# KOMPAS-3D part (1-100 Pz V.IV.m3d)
File: created 05.08.2017 09:44:06, last saved 05.08.2017 10:24:03.
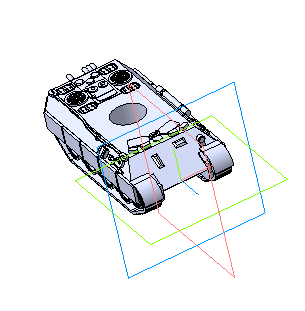
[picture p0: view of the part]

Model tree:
1. Операция без истории:1
2. Вырезать элемент выдавливания:1
     Расстояние 1 = 20
3. Вырезать элемент выдавливания:2
     Расстояние 1 = 20
4. Операция выдавливания:1
     Расстояние 1 = 0.1; Расстояние 2 = 1
5. Вырезать элемент выдавливания:3
     Расстояние 1 = 20
6. Вырезать элемент выдавливания:4
     Расстояние 1 = 17
7. Вырезать элемент выдавливания:5
     Расстояние 1 = 17
8. Вырезать элемент выдавливания:11
     Расстояние 1 = 19.2
9. Вырезать элемент выдавливания:12
     Расстояние 1 = 17
10. Вырезать элемент выдавливания:13
     Расстояние 1 = 17
11. Вырезать элемент выдавливания:14
     Расстояние 1 = 17
12. Вырезать элемент выдавливания:15
     Расстояние 1 = 19
13. Вырезать элемент выдавливания:16
     Расстояние 1 = 2
14. Вырезать элемент выдавливания:17
     Расстояние 1 = 0.4
15. Вырезать элемент выдавливания:18
     Расстояние 1 = 6
16. Эскиз:1
17. Вырезать элемент выдавливания:21
     Расстояние 1 = 1
18. Операция выдавливания:3
     Расстояние 1 = 0.8; Расстояние 2 = 17
19. Вырезать элемент выдавливания:22
     Расстояние 1 = 2
20. Вырезать элемент выдавливания:23
     Расстояние 1 = 2
21. Вырезать элемент выдавливания:24
     Расстояние 1 = 2
22. Вырезать элемент выдавливания:25
     Расстояние 1 = 1
23. Эскиз:2
24. Вырезать элемент выдавливания:26
     Расстояние 1 = 11
25. Эскиз:3
26. Операция выдавливания:4
     Расстояние 1 = 0.4; Расстояние 2 = 17
27. Уклон:1
     Угол уклона = 60
28. Уклон:2
     Угол уклона = 60
29. Уклон:3
     Угол уклона = 60
30. Уклон:4
     Угол уклона = 60
31. Уклон:5
     Угол уклона = 60
32. Вырезать элемент выдавливания:27
     Расстояние 1 = 1.2
33. Вырезать элемент выдавливания:28
     Расстояние 1 = 0.4
34. Вырезать элемент выдавливания:29
     Расстояние 1 = 10.4
35. Вырезать элемент выдавливания:30
     Расстояние 1 = 1
36. Вырезать элемент выдавливания:31
     Расстояние 1 = 11
37. Вырезать элемент выдавливания:32
     Расстояние 1 = 0.1
38. Вырезать элемент выдавливания:33
     Расстояние 1 = 1
39. Вырезать элемент выдавливания:34
     Расстояние 1 = 11
40. Вырезать элемент выдавливания:35
     Расстояние 1 = 0.1
41. Вырезать элемент выдавливания:36
     Расстояние 1 = 0.8
42. Вырезать элемент выдавливания:37
     Расстояние 1 = 0.8
43. Вырезать элемент выдавливания:38
     Расстояние 1 = 0.8
44. Эскиз:4
45. Операция выдавливания:5
     Расстояние 1 = 8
